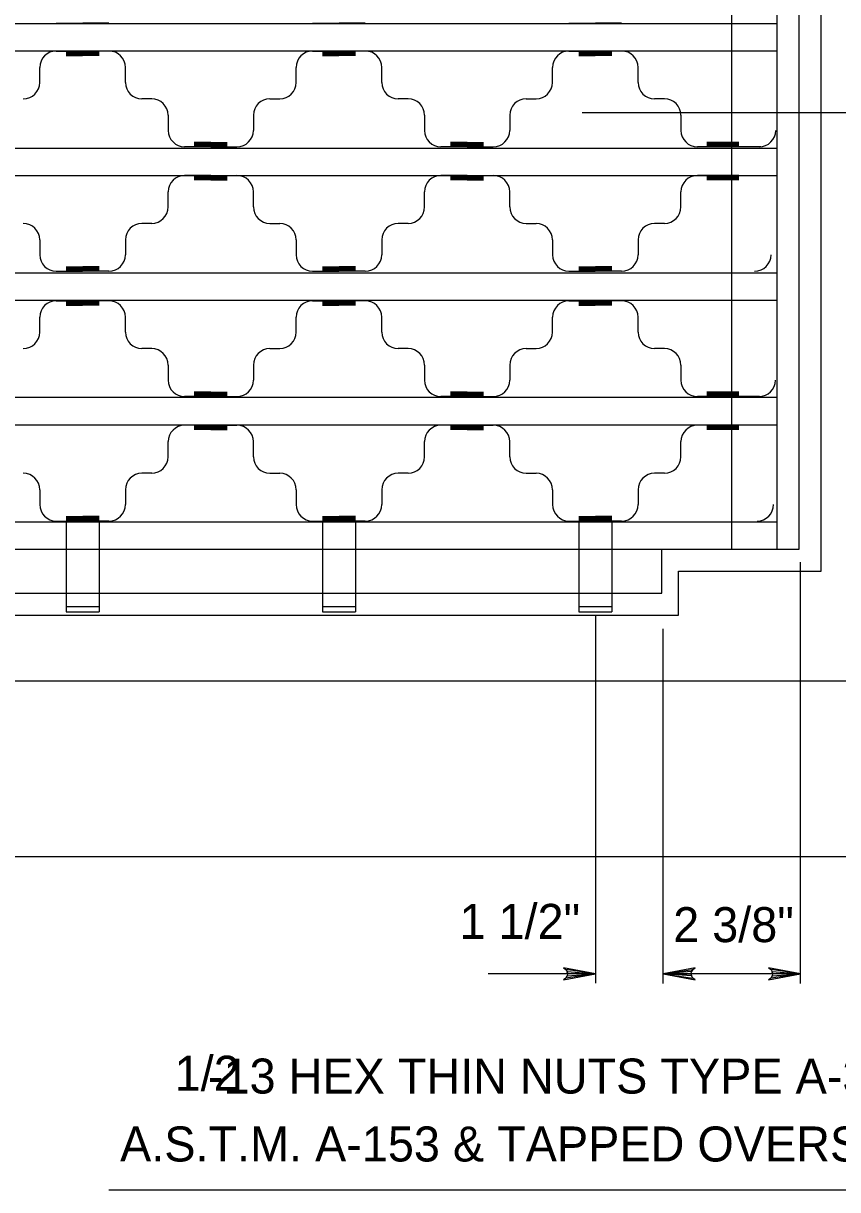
# Model space of a CAD drawing. Extents: x -0.3 to 6.9, y -6.5 to 3.5.
# Drawn here: x 3.055 to 4.451, y -1.25 to 0.751 of the extents above; entities that cross this region are included whole.
import ezdxf

# ---------------------------------------------------------------- set-up
doc = ezdxf.new("R2010")
doc.units = 0
for name, color, linetype in [('DETL-DIMS', 7, 'Continuous'), ('DETL-LINE', 7, 'Continuous'), ('DETL-NOTE', 7, 'Continuous')]:
    doc.layers.add(name, color=color, linetype=linetype)

msp = doc.modelspace()

# ---------------------------------------------------------------- linework, layer by layer
at = {"layer": 'DETL-DIMS'}
for p, q in [((4.9242, 0.5969), (4.0133, 0.5969)), ((4.3875, -0.8963), (4.3875, -0.1734)), ((4.0358, -0.2643), (4.0358, -0.8956)), ((4.1522, -0.8963), (4.1522, -0.2876)), ((4.0358, -0.8794), (3.8517, -0.8794)), ((4.3875, -0.8794), (4.1522, -0.8794))]:
    msp.add_line(p, q, dxfattribs=at)
for points in [[(4.0358, -0.8794), (3.981, -0.8691), (3.9852, -0.8721), (3.9874, -0.8757), (3.988, -0.8794), (3.9874, -0.8831), (3.9852, -0.8868), (3.981, -0.8897), (4.0358, -0.8794), (3.9852, -0.8868), (3.9874, -0.8831), (4.0358, -0.8794), (3.988, -0.8794), (3.9874, -0.8757), (4.0358, -0.8794), (3.9852, -0.8721)], [(4.1522, -0.8794), (4.2071, -0.8897), (4.2028, -0.8868), (4.2007, -0.8831), (4.2, -0.8794), (4.2007, -0.8757), (4.2028, -0.8721), (4.2071, -0.8691), (4.1522, -0.8794), (4.2028, -0.8721), (4.2007, -0.8757), (4.1522, -0.8794), (4.2, -0.8794), (4.2007, -0.8831), (4.1522, -0.8794), (4.2028, -0.8868)], [(4.3875, -0.8794), (4.3327, -0.8691), (4.3369, -0.8721), (4.3391, -0.8757), (4.3397, -0.8794), (4.3391, -0.8831), (4.3369, -0.8868), (4.3327, -0.8897), (4.3875, -0.8794), (4.3369, -0.8868), (4.3391, -0.8831), (4.3875, -0.8794), (4.3397, -0.8794), (4.3391, -0.8757), (4.3875, -0.8794), (4.3369, -0.8721)], [(4.3875, -0.8794), (4.3327, -0.8691), (4.3369, -0.8721), (4.3391, -0.8757), (4.3397, -0.8794), (4.3391, -0.8831), (4.3369, -0.8868), (4.3327, -0.8897), (4.3875, -0.8794), (4.3369, -0.8868), (4.3391, -0.8831), (4.3875, -0.8794), (4.3397, -0.8794), (4.3391, -0.8757), (4.3875, -0.8794), (4.3369, -0.8721)]]:
    msp.add_lwpolyline(points, dxfattribs=at)
at = {"layer": 'DETL-LINE'}
for p, q in [((4.4228, -0.189), (4.4228, 2.2863)), ((4.2695, -0.1513), (4.2695, 2.2487)), ((4.3475, -0.1513), (4.3475, 2.2487)), ((4.3851, -0.1513), (4.3851, 2.2487)), ((1.524, 0.7503), (4.3475, 0.7503)), ((3.1114, 0.7507), (3.1564, 0.7507)), ((3.2018, 0.7507), (3.1568, 0.7507)), ((3.5509, 0.7507), (3.596, 0.7507)), ((3.6413, 0.7507), (3.5963, 0.7507)), ((3.9905, 0.7507), (4.0355, 0.7507)), ((4.0808, 0.7507), (4.0358, 0.7507)), ((1.524, 0.7033), (4.3475, 0.7033)), ((3.1114, 0.7032), (3.1564, 0.7032)), ((3.1282, 0.7013), (3.1564, 0.7013)), ((3.2018, 0.7032), (3.1568, 0.7032)), ((3.185, 0.7013), (3.1568, 0.7013)), ((3.5509, 0.7032), (3.596, 0.7032)), ((3.5677, 0.7013), (3.596, 0.7013)), ((3.6413, 0.7032), (3.5963, 0.7032)), ((3.6245, 0.7013), (3.5963, 0.7013)), ((3.9905, 0.7032), (4.0355, 0.7032)), ((4.0072, 0.7013), (4.0355, 0.7013)), ((4.0808, 0.7032), (4.0358, 0.7032)), ((4.0641, 0.7013), (4.0358, 0.7013)), ((3.1282, 0.6994), (3.1564, 0.6994)), ((3.1282, 0.6975), (3.1564, 0.6975)), ((3.1282, 0.6957), (3.1564, 0.6957)), ((3.185, 0.6994), (3.1568, 0.6994)), ((3.185, 0.6975), (3.1568, 0.6975)), ((3.185, 0.6957), (3.1568, 0.6957)), ((3.5677, 0.6994), (3.596, 0.6994)), ((3.5677, 0.6975), (3.596, 0.6975)), ((3.5677, 0.6957), (3.596, 0.6957)), ((3.6245, 0.6994), (3.5963, 0.6994)), ((3.6245, 0.6975), (3.5963, 0.6975)), ((3.6245, 0.6957), (3.5963, 0.6957)), ((4.0072, 0.6994), (4.0355, 0.6994)), ((4.0072, 0.6975), (4.0355, 0.6975)), ((4.0072, 0.6957), (4.0355, 0.6957)), ((4.0641, 0.6994), (4.0358, 0.6994)), ((4.0641, 0.6975), (4.0358, 0.6975)), ((4.0641, 0.6957), (4.0358, 0.6957)), ((3.0832, 0.6494), (3.0832, 0.675)), ((3.23, 0.6494), (3.23, 0.675)), ((3.5227, 0.6494), (3.5227, 0.675)), ((3.6695, 0.6494), (3.6695, 0.675)), ((3.9622, 0.6494), (3.9622, 0.675)), ((4.1091, 0.6494), (4.1091, 0.675)), ((3.275, 0.6212), (3.2583, 0.6212)), ((3.4777, 0.6212), (3.4945, 0.6212)), ((3.7146, 0.6212), (3.6978, 0.6212)), ((3.9172, 0.6212), (3.934, 0.6212)), ((4.1541, 0.6212), (4.1373, 0.6212)), ((3.3033, 0.593), (3.3033, 0.5671)), ((3.4494, 0.593), (3.4494, 0.5671)), ((3.7428, 0.593), (3.7428, 0.5671)), ((3.889, 0.593), (3.889, 0.5671)), ((4.1823, 0.593), (4.1823, 0.5671)), ((3.3762, 0.5464), (3.348, 0.5464)), ((3.3762, 0.5445), (3.348, 0.5445)), ((3.3762, 0.5426), (3.348, 0.5426)), ((3.3762, 0.5407), (3.348, 0.5407)), ((3.3763, 0.5464), (3.4044, 0.5464)), ((3.3763, 0.5445), (3.4044, 0.5445)), ((3.3763, 0.5426), (3.4044, 0.5426)), ((3.3763, 0.5407), (3.4044, 0.5407)), ((3.8157, 0.5464), (3.7875, 0.5464)), ((3.8157, 0.5445), (3.7875, 0.5445)), ((3.8157, 0.5426), (3.7875, 0.5426)), ((3.8157, 0.5407), (3.7875, 0.5407)), ((3.8159, 0.5464), (3.844, 0.5464)), ((3.8159, 0.5445), (3.844, 0.5445)), ((3.8159, 0.5426), (3.844, 0.5426)), ((3.8159, 0.5407), (3.844, 0.5407)), ((4.2816, 0.5464), (4.227, 0.5464)), ((4.2816, 0.5445), (4.227, 0.5445)), ((4.2816, 0.5426), (4.227, 0.5426)), ((4.2816, 0.5407), (4.227, 0.5407)), ((1.524, 0.5367), (4.3475, 0.5367)), ((3.3762, 0.5388), (3.3315, 0.5388)), ((3.3763, 0.5388), (3.4212, 0.5388)), ((3.8157, 0.5388), (3.771, 0.5388)), ((3.8159, 0.5388), (3.8607, 0.5388)), ((4.3196, 0.5388), (4.2106, 0.5388)), ((1.524, 0.4896), (4.3475, 0.4896)), ((3.3762, 0.4898), (3.3315, 0.4898)), ((3.3762, 0.4879), (3.348, 0.4879)), ((3.3762, 0.486), (3.348, 0.486)), ((3.3762, 0.4841), (3.348, 0.4841)), ((3.3762, 0.4823), (3.348, 0.4823)), ((3.3763, 0.4898), (3.4212, 0.4898)), ((3.3763, 0.4879), (3.4044, 0.4879)), ((3.3763, 0.486), (3.4044, 0.486)), ((3.3763, 0.4841), (3.4044, 0.4841)), ((3.3763, 0.4823), (3.4044, 0.4823)), ((3.8157, 0.4898), (3.771, 0.4898)), ((3.8157, 0.4879), (3.7875, 0.4879)), ((3.8157, 0.486), (3.7875, 0.486)), ((3.8157, 0.4841), (3.7875, 0.4841)), ((3.8157, 0.4823), (3.7875, 0.4823)), ((3.8159, 0.4898), (3.8607, 0.4898)), ((3.8159, 0.4879), (3.844, 0.4879)), ((3.8159, 0.486), (3.844, 0.486)), ((3.8159, 0.4841), (3.844, 0.4841)), ((3.8159, 0.4823), (3.844, 0.4823)), ((4.2816, 0.4898), (4.2106, 0.4898)), ((4.2816, 0.4879), (4.227, 0.4879)), ((4.2816, 0.486), (4.227, 0.486)), ((4.2816, 0.4841), (4.227, 0.4841)), ((4.2816, 0.4823), (4.227, 0.4823)), ((3.3033, 0.4357), (3.3033, 0.4615)), ((3.4494, 0.4357), (3.4494, 0.4615)), ((3.7428, 0.4357), (3.7428, 0.4615)), ((3.889, 0.4357), (3.889, 0.4615)), ((4.1823, 0.4357), (4.1823, 0.4615)), ((3.275, 0.4074), (3.2583, 0.4074)), ((3.4777, 0.4074), (3.4945, 0.4074)), ((3.7146, 0.4074), (3.6978, 0.4074)), ((3.9172, 0.4074), (3.934, 0.4074)), ((4.1541, 0.4074), (4.1373, 0.4074)), ((3.0832, 0.3792), (3.0832, 0.3537)), ((3.23, 0.3792), (3.23, 0.3537)), ((3.5227, 0.3792), (3.5227, 0.3537)), ((3.6695, 0.3792), (3.6695, 0.3537)), ((3.9622, 0.3792), (3.9622, 0.3537)), ((4.1091, 0.3792), (4.1091, 0.3537)), ((1.524, 0.323), (4.3475, 0.323)), ((3.1114, 0.3254), (3.1564, 0.3254)), ((3.1282, 0.333), (3.1564, 0.333)), ((3.1282, 0.3311), (3.1564, 0.3311)), ((3.1282, 0.3292), (3.1564, 0.3292)), ((3.1282, 0.3273), (3.1564, 0.3273)), ((3.185, 0.333), (3.1568, 0.333)), ((3.185, 0.3311), (3.1568, 0.3311)), ((3.185, 0.3292), (3.1568, 0.3292)), ((3.185, 0.3273), (3.1568, 0.3273)), ((3.2018, 0.3254), (3.1568, 0.3254)), ((3.5509, 0.3254), (3.596, 0.3254)), ((3.5677, 0.333), (3.596, 0.333)), ((3.5677, 0.3311), (3.596, 0.3311)), ((3.5677, 0.3292), (3.596, 0.3292)), ((3.5677, 0.3273), (3.596, 0.3273)), ((3.6245, 0.333), (3.5963, 0.333)), ((3.6245, 0.3311), (3.5963, 0.3311)), ((3.6245, 0.3292), (3.5963, 0.3292)), ((3.6245, 0.3273), (3.5963, 0.3273)), ((3.6413, 0.3254), (3.5963, 0.3254)), ((3.9905, 0.3254), (4.0355, 0.3254)), ((4.0072, 0.333), (4.0355, 0.333)), ((4.0072, 0.3311), (4.0355, 0.3311)), ((4.0072, 0.3292), (4.0355, 0.3292)), ((4.0072, 0.3273), (4.0355, 0.3273)), ((4.0641, 0.333), (4.0358, 0.333)), ((4.0641, 0.3311), (4.0358, 0.3311)), ((4.0641, 0.3292), (4.0358, 0.3292)), ((4.0641, 0.3273), (4.0358, 0.3273)), ((4.0808, 0.3254), (4.0358, 0.3254)), ((1.524, 0.2761), (4.3475, 0.2761)), ((1.524, 0.276), (4.3475, 0.276)), ((3.1114, 0.2748), (3.1564, 0.2748)), ((3.1282, 0.2729), (3.1564, 0.2729)), ((3.1282, 0.271), (3.1564, 0.271)), ((3.1282, 0.2692), (3.1564, 0.2692)), ((3.1282, 0.2673), (3.1564, 0.2673)), ((3.2018, 0.2748), (3.1568, 0.2748)), ((3.185, 0.2729), (3.1568, 0.2729)), ((3.185, 0.271), (3.1568, 0.271)), ((3.185, 0.2692), (3.1568, 0.2692)), ((3.185, 0.2673), (3.1568, 0.2673)), ((3.5509, 0.2748), (3.596, 0.2748)), ((3.5677, 0.2729), (3.596, 0.2729)), ((3.5677, 0.271), (3.596, 0.271)), ((3.5677, 0.2692), (3.596, 0.2692)), ((3.5677, 0.2673), (3.596, 0.2673)), ((3.6413, 0.2748), (3.5963, 0.2748)), ((3.6245, 0.2729), (3.5963, 0.2729)), ((3.6245, 0.271), (3.5963, 0.271)), ((3.6245, 0.2692), (3.5963, 0.2692)), ((3.6245, 0.2673), (3.5963, 0.2673)), ((3.9905, 0.2748), (4.0355, 0.2748)), ((4.0072, 0.2729), (4.0355, 0.2729)), ((4.0072, 0.271), (4.0355, 0.271)), ((4.0072, 0.2692), (4.0355, 0.2692)), ((4.0072, 0.2673), (4.0355, 0.2673)), ((4.0808, 0.2748), (4.0358, 0.2748)), ((4.0641, 0.2729), (4.0358, 0.2729)), ((4.0641, 0.271), (4.0358, 0.271)), ((4.0641, 0.2692), (4.0358, 0.2692)), ((4.0641, 0.2673), (4.0358, 0.2673)), ((3.0832, 0.2211), (3.0832, 0.2466)), ((3.23, 0.2211), (3.23, 0.2466)), ((3.5227, 0.2211), (3.5227, 0.2466)), ((3.6695, 0.2211), (3.6695, 0.2466)), ((3.9622, 0.2211), (3.9622, 0.2466)), ((4.1091, 0.2211), (4.1091, 0.2466)), ((3.275, 0.1928), (3.2583, 0.1928)), ((3.4777, 0.1928), (3.4945, 0.1928)), ((3.7146, 0.1928), (3.6978, 0.1928)), ((3.9172, 0.1928), (3.934, 0.1928)), ((4.1541, 0.1928), (4.1373, 0.1928)), ((3.3033, 0.1646), (3.3033, 0.1387)), ((3.4494, 0.1646), (3.4494, 0.1387)), ((3.7428, 0.1646), (3.7428, 0.1387)), ((3.889, 0.1646), (3.889, 0.1387)), ((4.1823, 0.1646), (4.1823, 0.1387)), ((1.524, 0.1095), (4.3475, 0.1095)), ((1.524, 0.1094), (4.3475, 0.1094)), ((3.3762, 0.1105), (3.3315, 0.1105)), ((3.3762, 0.118), (3.348, 0.118)), ((3.3762, 0.1161), (3.348, 0.1161)), ((3.3762, 0.1142), (3.348, 0.1142)), ((3.3762, 0.1123), (3.348, 0.1123)), ((3.3763, 0.118), (3.4044, 0.118)), ((3.3763, 0.1161), (3.4044, 0.1161)), ((3.3763, 0.1142), (3.4044, 0.1142)), ((3.3763, 0.1123), (3.4044, 0.1123)), ((3.3763, 0.1105), (3.4212, 0.1105)), ((3.8157, 0.1105), (3.771, 0.1105)), ((3.8157, 0.118), (3.7875, 0.118)), ((3.8157, 0.1161), (3.7875, 0.1161)), ((3.8157, 0.1142), (3.7875, 0.1142)), ((3.8157, 0.1123), (3.7875, 0.1123)), ((3.8159, 0.118), (3.844, 0.118)), ((3.8159, 0.1161), (3.844, 0.1161)), ((3.8159, 0.1142), (3.844, 0.1142)), ((3.8159, 0.1123), (3.844, 0.1123)), ((3.8159, 0.1105), (3.8607, 0.1105)), ((4.3171, 0.1105), (4.2106, 0.1105)), ((4.2816, 0.118), (4.227, 0.118)), ((4.2816, 0.1161), (4.227, 0.1161)), ((4.2816, 0.1142), (4.227, 0.1142)), ((4.2816, 0.1123), (4.227, 0.1123)), ((1.524, 0.0623), (4.3475, 0.0623)), ((3.3762, 0.0614), (3.3315, 0.0614)), ((3.3763, 0.0614), (3.4212, 0.0614)), ((3.8157, 0.0614), (3.771, 0.0614)), ((3.8159, 0.0614), (3.8607, 0.0614)), ((4.2816, 0.0614), (4.2106, 0.0614)), ((3.3762, 0.0595), (3.348, 0.0595)), ((3.3762, 0.0576), (3.348, 0.0576)), ((3.3762, 0.0558), (3.348, 0.0558)), ((3.3762, 0.0539), (3.348, 0.0539)), ((3.3763, 0.0595), (3.4044, 0.0595)), ((3.3763, 0.0576), (3.4044, 0.0576)), ((3.3763, 0.0558), (3.4044, 0.0558)), ((3.3763, 0.0539), (3.4044, 0.0539)), ((3.8157, 0.0595), (3.7875, 0.0595)), ((3.8157, 0.0576), (3.7875, 0.0576)), ((3.8157, 0.0558), (3.7875, 0.0558)), ((3.8157, 0.0539), (3.7875, 0.0539)), ((3.8159, 0.0595), (3.844, 0.0595)), ((3.8159, 0.0576), (3.844, 0.0576)), ((3.8159, 0.0558), (3.844, 0.0558)), ((3.8159, 0.0539), (3.844, 0.0539)), ((4.2816, 0.0595), (4.227, 0.0595)), ((4.2816, 0.0576), (4.227, 0.0576)), ((4.2816, 0.0558), (4.227, 0.0558)), ((4.2816, 0.0539), (4.227, 0.0539)), ((3.3033, 0.0073), (3.3033, 0.0332)), ((3.4494, 0.0073), (3.4494, 0.0332)), ((3.7428, 0.0073), (3.7428, 0.0332)), ((3.889, 0.0073), (3.889, 0.0332)), ((4.1823, 0.0073), (4.1823, 0.0332)), ((3.275, -0.021), (3.2583, -0.021)), ((3.4777, -0.021), (3.4945, -0.021)), ((3.7146, -0.021), (3.6978, -0.021)), ((3.9172, -0.021), (3.934, -0.021)), ((4.1541, -0.021), (4.1373, -0.021)), ((3.0832, -0.0492), (3.0832, -0.0747)), ((3.23, -0.0492), (3.23, -0.0747)), ((3.5227, -0.0492), (3.5227, -0.0747)), ((3.6695, -0.0492), (3.6695, -0.0747)), ((3.9622, -0.0492), (3.9622, -0.0747)), ((4.1091, -0.0492), (4.1091, -0.0747)), ((3.1282, -0.0954), (3.1564, -0.0954)), ((3.1282, -0.0973), (3.1564, -0.0973)), ((3.1282, -0.0992), (3.1564, -0.0992)), ((3.185, -0.0954), (3.1568, -0.0954)), ((3.185, -0.0973), (3.1568, -0.0973)), ((3.185, -0.0992), (3.1568, -0.0992)), ((3.5677, -0.0954), (3.596, -0.0954)), ((3.5677, -0.0973), (3.596, -0.0973)), ((3.5677, -0.0992), (3.596, -0.0992)), ((3.6245, -0.0954), (3.5963, -0.0954)), ((3.6245, -0.0973), (3.5963, -0.0973)), ((3.6245, -0.0992), (3.5963, -0.0992)), ((4.0072, -0.0954), (4.0355, -0.0954)), ((4.0072, -0.0973), (4.0355, -0.0973)), ((4.0072, -0.0992), (4.0355, -0.0992)), ((4.0641, -0.0954), (4.0358, -0.0954)), ((4.0641, -0.0973), (4.0358, -0.0973)), ((4.0641, -0.0992), (4.0358, -0.0992)), ((1.524, -0.1043), (4.3475, -0.1043)), ((3.1114, -0.1029), (3.1564, -0.1029)), ((3.1282, -0.1011), (3.1564, -0.1011)), ((3.1282, -0.1043), (3.1282, -0.2588)), ((3.185, -0.1011), (3.1568, -0.1011)), ((3.2018, -0.1029), (3.1568, -0.1029)), ((3.185, -0.1043), (3.185, -0.2588)), ((3.5509, -0.1029), (3.596, -0.1029)), ((3.5677, -0.1011), (3.596, -0.1011)), ((3.5678, -0.1042), (3.5678, -0.2587)), ((3.6245, -0.1011), (3.5963, -0.1011)), ((3.6413, -0.1029), (3.5963, -0.1029)), ((3.6246, -0.1042), (3.6246, -0.2587)), ((3.9905, -0.1029), (4.0355, -0.1029)), ((4.0072, -0.1011), (4.0355, -0.1011)), ((4.0074, -0.1043), (4.0074, -0.2588)), ((4.0641, -0.1011), (4.0358, -0.1011)), ((4.0808, -0.1029), (4.0358, -0.1029)), ((4.0642, -0.1043), (4.0642, -0.2588)), ((1.4863, -0.1513), (4.3851, -0.1513)), ((4.1498, -0.2266), (4.1498, -0.1513)), ((4.1781, -0.189), (4.4228, -0.189)), ((4.1781, -0.2643), (4.1781, -0.189)), ((1.7216, -0.2266), (4.1498, -0.2266)), ((3.1282, -0.2494), (3.185, -0.2494)), ((3.1282, -0.2588), (3.185, -0.2588)), ((3.5678, -0.2493), (3.6246, -0.2493)), ((3.5678, -0.2587), (3.6246, -0.2587)), ((4.0074, -0.2494), (4.0642, -0.2494)), ((4.0074, -0.2588), (4.0642, -0.2588)), ((1.6934, -0.2643), (4.1781, -0.2643)), ((1.3734, -0.3772), (4.4981, -0.3772)), ((1.0722, -0.6784), (4.7992, -0.6784))]:
    msp.add_line(p, q, dxfattribs=at)
for centre, start, end in [((3.1114, 0.675), 90, 180), ((3.2018, 0.675), 0, 90), ((3.5509, 0.675), 90, 180), ((3.6413, 0.675), 0, 90), ((3.9905, 0.675), 90, 180), ((4.0808, 0.675), 0, 90), ((3.0549, 0.6494), 270, 0), ((3.2583, 0.6494), 180, 270), ((3.4945, 0.6494), 270, 0), ((3.6978, 0.6494), 180, 270), ((3.934, 0.6494), 270, 0), ((4.1373, 0.6494), 180, 270), ((3.275, 0.593), 0, 90), ((3.4777, 0.593), 90, 180), ((3.7146, 0.593), 0, 90), ((3.9172, 0.593), 90, 180), ((4.1541, 0.593), 0, 90), ((3.3315, 0.5671), 180, 270), ((3.4212, 0.5671), 270, 0), ((3.771, 0.5671), 180, 270), ((3.8607, 0.5671), 270, 0), ((4.2106, 0.5671), 180, 270), ((4.3167, 0.5671), 270, 0), ((3.3315, 0.4615), 90, 180), ((3.4212, 0.4615), 0, 90), ((3.771, 0.4615), 90, 180), ((3.8607, 0.4615), 0, 90), ((4.2106, 0.4615), 90, 180), ((3.275, 0.4357), 270, 0), ((3.4777, 0.4357), 180, 270), ((3.7146, 0.4357), 270, 0), ((3.9172, 0.4357), 180, 270), ((4.1541, 0.4357), 270, 0), ((3.0549, 0.3792), 0, 90), ((3.2583, 0.3792), 90, 180), ((3.4945, 0.3792), 0, 90), ((3.6978, 0.3792), 90, 180), ((3.934, 0.3792), 0, 90), ((4.1373, 0.3792), 90, 180), ((3.1114, 0.3537), 180, 270), ((3.2018, 0.3537), 270, 0), ((3.5509, 0.3537), 180, 270), ((3.6413, 0.3537), 270, 0), ((3.9905, 0.3537), 180, 270), ((4.0808, 0.3537), 270, 0), ((4.3088, 0.3537), 270, 0), ((3.1114, 0.2466), 90, 180), ((3.2018, 0.2466), 0, 90), ((3.5509, 0.2466), 90, 180), ((3.6413, 0.2466), 0, 90), ((3.9905, 0.2466), 90, 180), ((4.0808, 0.2466), 0, 90), ((3.0549, 0.2211), 270, 0), ((3.2583, 0.2211), 180, 270), ((3.4945, 0.2211), 270, 0), ((3.6978, 0.2211), 180, 270), ((3.934, 0.2211), 270, 0), ((4.1373, 0.2211), 180, 270), ((3.275, 0.1646), 0, 90), ((3.4777, 0.1646), 90, 180), ((3.7146, 0.1646), 0, 90), ((3.9172, 0.1646), 90, 180), ((4.1541, 0.1646), 0, 90), ((3.3315, 0.1387), 180, 270), ((3.4212, 0.1387), 270, 0), ((3.771, 0.1387), 180, 270), ((3.8607, 0.1387), 270, 0), ((4.2106, 0.1387), 180, 270), ((4.3163, 0.1387), 270, 0), ((3.3315, 0.0332), 90, 180), ((3.4212, 0.0332), 0, 90), ((3.771, 0.0332), 90, 180), ((3.8607, 0.0332), 0, 90), ((4.2106, 0.0332), 90, 180), ((3.275, 0.0073), 270, 0), ((3.4777, 0.0073), 180, 270), ((3.7146, 0.0073), 270, 0), ((3.9172, 0.0073), 180, 270), ((4.1541, 0.0073), 270, 0), ((3.0549, -0.0492), 0, 90), ((3.2583, -0.0492), 90, 180), ((3.4945, -0.0492), 0, 90), ((3.6978, -0.0492), 90, 180), ((3.934, -0.0492), 0, 90), ((4.1373, -0.0492), 90, 180), ((3.1114, -0.0747), 180, 270), ((3.2018, -0.0747), 270, 0), ((3.5509, -0.0747), 180, 270), ((3.6413, -0.0747), 270, 0), ((3.9905, -0.0747), 180, 270), ((4.0808, -0.0747), 270, 0), ((4.3131, -0.0747), 270, 0)]:
    msp.add_arc(centre, 0.0282, start, end, dxfattribs=at)
at = {"layer": 'DETL-NOTE'}
msp.add_line((3.2016, -1.2498), (6.8521, -1.2498), dxfattribs=at)

# ---------------------------------------------------------------- texts
for s, p in [('1 1/2"', (3.8028, -0.8196)), ('2 3/8"', (4.1692, -0.8252)), ('1/2', (3.3144, -1.08)), (' -13 HEX THIN NUTS TYPE A-307 STEEL GALVANIZED AS PER', (3.3492, -1.0849)), ('A.S.T.M. A-153 & TAPPED OVERSIZE TO FIT 1/2" O GALVANIZED STUD', (3.2208, -1.2014))]:
    msp.add_text(s, height=0.06, dxfattribs=at).set_placement(p)

doc.saveas('drawing.dxf')
